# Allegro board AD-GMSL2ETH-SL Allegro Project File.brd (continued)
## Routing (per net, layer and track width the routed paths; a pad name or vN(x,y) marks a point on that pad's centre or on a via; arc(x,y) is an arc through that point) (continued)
B_SIOAN: length 2
  BOTTOM w0.127: C57.1 114.18,33.74 U2.22
B_SIOAP: length 2
  BOTTOM w0.127: U2.23 113.8,33.42 C63.2
B_SIOBN: length 2
  BOTTOM w0.127: U2.19 115.25,34.8 C58.1
B_SIOBP: length 2
  BOTTOM w0.127: C64.2 115.62,35.14 U2.18
B_SIOCN: length 2
  BOTTOM w0.127: C59.1 114.92,41.44 U2.9
B_SIOCP: length 2
  BOTTOM w0.127: C61.2 115.25,41.06 U2.10
B_SIODN: length 2
  BOTTOM w0.127: U2.6 113.84,42.48 C60.1
B_SIODP: length 2
  BOTTOM w0.127: C62.2 113.5,42.85 U2.5
B_VDD18: length 29.2
  TOP w0.483: C80.1 C79.1 v1(112.57,35.84) ; v1(112.21,40.38) 111.88,40.05 C67.1 C66.1
  TOP w0.508: 113.11,35.3 112.58,35.84 v1(112.57,35.84) ; 112.24,41.6 111.29,40.65 C66.1
  TOP w0.61: 113.11,35.3 113.52,34.9 118.68,34.9 119.04,35.26 C154.1 ; 112.24,41.6 114.2,43.56 C65.1 R22.2
  L3_SIG w0.508: v1(112.21,40.38) 111.86,40.03 111.86,39.73 113.31,38.28 113.31,37.56 112.24,36.5 112.24,36.17 v1(112.57,35.84)
  BOTTOM w0.305: U2.7 112.5,40.43 112.26,40.43 v1(112.21,40.38) ; U2.21 112.85,35.79 112.62,35.79 v1(112.57,35.84)
B_VPOC_1: length 4.5
  TOP w0.305: 139.47,17.86 139.88,18.27 U13.6
  TOP w0.508: C89.1 139.47,17.15 139.47,17.86
  TOP w0.762: R216.1 C89.1
B_VPOC_2: length 4.6
  TOP w0.305: 139.5,23.5 139.88,23.11 U13.20
  TOP w0.508: C88.1 139.5,24.01 139.5,23.5
  TOP w0.762: C88.1 138.92,24.55 R231.1
B_VPOC_3: length 4.5
  TOP w0.305: 140.77,17.86 140.38,18.24 U13.7
  TOP w0.508: C90.1 140.77,17.15 140.77,17.86
  TOP w0.762: R214.1 C90.1
B_VPOC_4: length 4.7
  TOP w0.305: 140.79,23.5 140.38,23.09 U13.19
  TOP w0.508: C91.1 140.79,24.03 140.79,23.5
  TOP w0.762: C91.1 141.34,24.55 R215.1
B_VTERM: length 1.3
  BOTTOM w0.305: 108.89,32.22 108.89,32.58 U2.30
BTN0_USER: length 55.8
  TOP w0.203: P5.C52 v2(100.77,28.95)
  TOP w0.508: v1(137.44,12.55) R218.2 S3.2 S3.1
  BOTTOM w0.305: v2(100.77,28.95) 103.13,28.95 104.29,27.79 104.29,25.25 107.82,21.72 115.67,21.72 118.77,18.62 131.37,18.62 v1(137.44,12.55)
EN_5V0: length 79.6
  TOP w0.305: v1(35.81,47.34) 36.22,47.75 U21.10 ; U10.20 v1(33.1,90.3)
  L8_SIG w0.508: v1(35.81,47.34) 32.68,50.46 32.68,67.68 27.01,73.36 27.01,89.01 29.09,91.1 29.09,91.11 29.5,91.52 32.82,91.52 33.18,91.16 33.18,90.38 v1(33.1,90.3)
  BOTTOM w0.508: v1(35.18,109.8) 32.46,107.09 32.46,100.84 35.18,98.12 35.18,92.37 v1(33.1,90.3)
EN_I2C_ALT: length 68.4
  TOP w0.203: U25.5 v2(117.93,22.82) 104.84,22.82 P5.A54 ; v1(113.99,66.63) R41.2 U20.5
  L3_SIG w0.203: v1(113.99,66.63) 113.99,56.76 120.82,49.93 120.82,46.21 119.96,45.35 119.96,32.99 120.49,32.46 120.49,28.53 118.58,26.63 118.58,23.39 118.02,22.82 v2(117.93,22.82)
EN_VIO: length 46.9
  TOP w0.254: v1(15.01,45.75) v1(23.83,45.75) 26.44,43.13 31.78,43.13 32.71,44.06 v1(32.71,44.97) 34.59,44.97 36.42,43.13 40.71,43.13 41.6,44.03 v1(41.6,44.97) 46.22,49.59 R220.2 U26.6 47.96,50.39 48.21,50.64 48.21,51.43 47.96,51.69 U26.4
  BOTTOM w0.254: v1(32.71,44.97) 32.97,44.71 U18.1 ; v1(15.01,45.75) 15.01,45.06 15.19,44.88 U4.1 ; v1(41.6,44.97) 41.86,44.71 U5.1 ; v1(23.83,45.75) 23.83,44.96 24.08,44.71 U6.1
FAN_PWM: length 52.5
  TOP w0.203: P3.C23 v2(82.04,94.6)
  BOTTOM w0.305: R98.1 61.76,53.73 62.28,54.25 62.28,69.6 82.04,89.36 v2(82.04,94.6)
FAN_TACH: length 54.4
  TOP w0.203: P3.C22 v2(81.4,94.6)
  TOP w0.305: v1(61.65,56.79) R104.1
  TOP w0.356: R103.2 54.38,56.86 R104.1
  BOTTOM w0.305: v1(61.65,56.79) 61.65,70.02 81.4,89.77 v2(81.4,94.6)
GPIO_0: length 71.5
  TOP w0.203: P3.A15 v2(76.96,92.06)
  TOP w0.508: D7.3 v1(17.43,70.79)
  TOP w0.61: D7.3 RT3.2
  L3_SIG w0.203: v1(17.43,70.79) 17.98,71.35 24.14,71.35 30.72,77.93 42.74,77.93 48.48,83.67 69.27,83.67 76.96,91.36 v2(76.96,92.06)
GPIO_1: length 77.3
  TOP w0.203: P3.A16 v2(77.59,92.06)
  TOP w0.508: D8.3 v1(17.43,73.79)
  TOP w0.61: D8.3 RT4.2
  L3_SIG w0.203: v2(77.59,92.06) 77.59,91.18 69.49,83.08 48.74,83.08 43,77.34 30.92,77.34 23.81,70.23 16.87,70.23 16.46,70.64 16.46,72.82 v1(17.43,73.79)
GPIO_2: length 85.8
  TOP w0.203: P3.A17 v2(78.23,92.06)
  TOP w0.508: D9.3 v1(17.43,80.04)
  TOP w0.61: D9.3 RT5.2
  L3_SIG w0.203: v1(17.43,80.04) 15.85,78.46 15.85,70.33 16.41,69.77 24.09,69.77 31.08,76.76 43.28,76.76 49.02,82.5 69.75,82.5 78.23,90.98 v2(78.23,92.06)
GPIO_3: length 78.8
  TOP w0.203: P3.B16 v2(77.59,93.9)
  TOP w0.508: D10.3 v1(17.43,83.19)
  TOP w0.61: D10.3 RT6.2
  L3_SIG w0.203: v1(17.43,83.19) 18.62,81.99 18.62,75.74 19.6,74.76 25.16,74.76 30.09,79.68 40.67,79.68 46.39,85.4 68.44,85.4 74.88,91.85 74.88,92.84 75.5,93.46 77.39,93.46 77.59,93.66 v2(77.59,93.9)
GPIO_4: length 84.5
  TOP w0.203: P3.B17 v2(78.23,93.99)
  TOP w0.508: D11.3 v1(17.43,86.33)
  TOP w0.61: D11.3 RT7.2
  L3_SIG w0.203: v2(78.23,93.99) 78.23,93.62 77.61,93.01 75.84,93.01 75.36,92.53 75.36,91.44 68.75,84.83 46.63,84.83 40.92,79.11 30.41,79.11 25.59,74.3 19.18,74.3 18.01,75.46 18.01,81.41 16.51,82.91 16.51,85.42 v1(17.43,86.33)
GPIO_5: length 87.2
  TOP w0.203: P3.B18 78.86,93.8 79.09,94.03 v2(79.81,94.03)
  TOP w0.508: D12.3 v1(17.43,89.48)
  TOP w0.61: D12.3 RT8.2
  L3_SIG w0.203: v1(17.43,89.48) 18.35,88.56 20.62,88.56 21.46,87.71 21.46,83.54 22.17,82.83 27.66,82.83 30.02,85.19 33.25,85.19 34.16,84.28 39.24,84.28 44.73,89.76 61.21,89.76 62.61,91.16 62.61,95.22 65.86,98.48 80.01,98.48 81.38,97.1 81.38,95.69 80.62,94.93 80.62,94.23 80.42,94.03 v2(79.81,94.03)
GPIO_6: length 74.9
  TOP w0.203: P3.C18 v2(78.86,94.6)
  TOP w0.508: D14.3 v1(20.25,72.21)
  TOP w0.61: D14.3 RT11.2
  L3_SIG w0.203: v1(20.25,72.21) 20.93,72.9 25.01,72.9 30.64,78.53 41.21,78.53 46.91,84.23 69,84.23 75.84,91.07 75.84,92.23 76.23,92.61 77.8,92.61 78.86,93.67 v2(78.86,94.6)
GPIO_7: length 76.9
  TOP w0.203: P3.C19 v2(79.5,94.6)
  TOP w0.61: D15.3 19.7,76.12 v1(19.3,76.12) RT12.2
  L3_SIG w0.203: v1(19.3,76.12) 21.01,76.12 22.12,77.24 26.78,77.24 30.34,80.8 39.53,80.8 45.58,86.85 62.52,86.85 65.58,89.92 65.58,94.69 66.47,95.58 78.94,95.58 79.5,95.02 v2(79.5,94.6)
GPIO_8: length 77.1
  TOP w0.203: P3.C20 v2(80.13,94.6)
  TOP w0.61: D16.3 19.7,77.7 v1(19.3,77.7) RT13.2
  L3_SIG w0.203: v2(80.13,94.6) 80.13,94.97 79.12,95.99 66.19,95.99 65.02,94.82 65.02,90.2 62.23,87.4 45.37,87.4 39.32,81.36 30.19,81.36 26.53,77.7 v1(19.3,77.7)
GPIO_9: length 74.3
  TOP w0.203: P3.D16 v2(77.59,96.53)
  TOP w0.508: D17.3 v1(20.25,81.7)
  TOP w0.61: D17.3 RT14.2
  L3_SIG w0.203: v1(20.25,81.7) 22.16,79.78 27.8,79.78 29.96,81.94 39.17,81.94 45.2,87.97 62.01,87.97 64.41,90.37 64.41,94.87 66.72,97.17 77.28,97.17 77.59,96.85 v2(77.59,96.53)
GPIO_10: length 77.1
  TOP w0.203: P3.D17 v2(78.23,96.53)
  TOP w0.508: D18.3 v1(20.25,84.76)
  TOP w0.61: D18.3 RT15.2
  L3_SIG w0.203: v1(20.25,84.76) 20.25,82.8 22.73,80.31 27.52,80.31 29.73,82.52 38.99,82.52 45.04,88.57 61.75,88.57 63.8,90.63 63.8,94.95 66.48,97.62 77.56,97.62 78.23,96.95 v2(78.23,96.53)
GPIO_11: length 79.2
  TOP w0.203: P3.D18 v2(78.86,96.53)
  TOP w0.508: D19.3 v1(20.25,87.91)
  TOP w0.61: D19.3 RT16.2
  L3_SIG w0.203: v2(78.86,96.53) 78.86,97.11 77.9,98.07 66.19,98.07 63.2,95.07 63.2,90.88 61.48,89.17 44.9,89.17 39.48,83.74 29.44,83.74 27.86,82.17 21.82,82.17 20.87,83.12 20.87,87.28 v1(20.25,87.91)
GTH_REFLCK_N: length 99.9
  TOP w0.203: P5.C4 v4(70.29,28.95)
  L3_SIG w0.203: v1(103.3,104.09) 103.3,101.13 102.22,100.05 102.22,98.43 101.45,97.66 96.24,97.66 95.21,96.63 95.21,92.47 67.77,65.03 67.77,27.99 68.51,27.25 69.54,27.25 70.17,27.89 70.17,28.56 70.29,28.68 v4(70.29,28.95)
  BOTTOM w0.203: C128.2 102.78,103.57 v1(103.3,104.09)
GTH_REFLCK_P: length 93.6
  TOP w0.203: P5.C3 v4(69.66,28.95)
  L3_SIG w0.203: v4(69.66,28.95) 69.66,28.67 69.78,28.55 69.78,28.09 69.36,27.67 68.68,27.67 68.19,28.17 68.19,64.78 95.63,92.22 95.63,96.46 96.41,97.24 101.63,97.24 102.64,98.25 102.64,99.62 v1(103.25,100.23)
  BOTTOM w0.203: C127.2 v1(103.25,100.23)
I2C_EXP_RSTB: length 59.1
  TOP w0.203: R121.2 v2(132.82,58.01) 133.43,58.62 U19.24 ; P5.C51 v2(100.14,28.95)
  L8_SIG w0.203: v2(132.82,58.01) 132.82,56.67 133.27,56.21 133.27,53.87 118.17,38.76 117.5,38.76 115.7,40.56 114.73,40.56 114.33,40.16 114.33,38.99 115.47,37.85 115.47,30.78 115.04,30.35 106.18,30.35 105.24,29.41 100.34,29.41 100.14,29.21 v2(100.14,28.95)
I2C_MASTER_SCL: length 3.9
  TOP w0.203: U3.33 95.61,110.66 v2(95.86,110.91) 96.1,111.15 R45.2
  BOTTOM w0.203: v2(95.86,110.91) 96.36,111.41 R54.2
I2C_MASTER_SDA: length 3.9
  TOP w0.203: R42.2 94.12,111.15 v2(94.36,110.91) 94.61,110.66 U3.35
  BOTTOM w0.203: R58.2 93.86,111.41 v2(94.36,110.91)
I2C_SCK: length 55.2
  TOP w0.203: R119.2 v2(130.61,61.72) R122.1 ; P5.D49 98.55,29.44 98.78,29.67 98.78,30.45 v2(99.59,31.27)
  L8_SIG w0.203: v2(99.59,31.27) 99.59,35.38 103.23,39.01 105.61,39.01 109.6,43 121.23,43 129.29,51.06 129.29,60.4 v2(130.61,61.72)
I2C_SDA: length 54.3
  TOP w0.203: v2(99.59,30.61) 99.18,30.21 P5.D50 ; R123.1 131.31,60.93 v2(130.61,60.93) 130.61,60.94 R120.2
  L8_SIG w0.203: v2(130.61,60.93) 129.72,60.05 129.72,50.89 121.4,42.57 109.8,42.57 105.84,38.61 103.41,38.61 100.1,35.3 100.1,30.82 99.9,30.61 v2(99.59,30.61)
JTAG_TCK: length 45.3
  TOP w0.203: P3.A25 83.31,88.8 80.98,86.46 57.76,86.46 54.38,83.08 51.05,83.08 50.65,83.49 50.65,87.76 50.97,88.08 P7.6
JTAG_TDI: length 35.6
  TOP w0.203: P3.A24 82.67,89.13 80.65,87.1 57.48,87.1 54.46,84.08 P7.10
JTAG_TDO: length 34
  TOP w0.203: P7.8 55.5,86.08 57.15,87.73 80.34,87.73 82.04,89.43 P3.A23
JTAG_TMS: length 32.9
  TOP w0.203: P7.4 55.49,90.08 57.2,88.37 80.04,88.37 81.4,89.74 P3.A22
LDO_OUT: length 1.3
  TOP w0.483: R239.2 40.16,49.47 C249.1
LED0_USER: length 11.4
  TOP w0.203: P5.B53 101.4,26.42 v2(102.03,26.42)
  TOP w0.406: v1(102.03,20.22) 100.84,20.22 100.32,19.7 R152.1 Q3.1
  L8_SIG w0.305: v1(102.03,20.22) v2(102.03,26.42)
MIO36_TXD: length 94
  TOP w0.203: v2(95.23,19.78) 95.23,18.93 90.78,14.47 U24.8 ; P3.B29 v2(85.85,93.99)
  BOTTOM w0.203: v2(95.23,19.78) 92.21,19.78 90.02,21.97 90.02,38.81 82.5,46.33 82.5,85.73 86.98,90.21 86.98,92.29 85.85,93.42 v2(85.85,93.99)
MIO37_RXD: length 92.2
  TOP w0.203: P3.B30 v2(86.48,93.99) ; v2(94.72,20.31) 94.72,19.13 90.57,14.97 U24.9
  BOTTOM w0.203: v2(94.72,20.31) 92.42,20.31 90.54,22.19 90.54,39.03 83.02,46.55 83.02,85.51 87.42,89.9 87.42,92.59 86.48,93.52 v2(86.48,93.99)
OUT0_A_N: length 4
  TOP w0.203: U3.12 99.61,102.11 99.81,101.9 v2(100.33,101.9)
  BOTTOM w0.203: v2(100.33,101.9) 101.94,101.9 R53.2 102.15,102.11 C128.1
OUT0_A_P: length 4.8
  TOP w0.203: v2(100.33,101.3) 99.8,101.3 99.11,101.98 U3.11
  BOTTOM w0.203: C127.1 102.15,101.09 R52.1 101.94,101.3 v2(100.33,101.3)
OUT0_B_N: length 6
  TOP w0.203: R91.1 R87.2 104.56,102.31 104.27,102.31 102.3,104.27 U3.15
OUT0_B_P: length 6
  TOP w0.203: U3.14 102.1,103.77 104.07,101.8 104.56,101.8 R86.1 R90.1
OUT0_C_N: length 5.4
  TOP w0.203: C150.1 104.81,106.05 R208.2 104.54,105.77 U3.18
OUT0_C_P: length 5.4
  TOP w0.203: U3.17 104.54,105.27 R207.2 104.81,105 C149.1
OUT1_A_N: length 4.6
  TOP w0.203: U3.26 99.11,110.06 99.8,110.75 v2(100.33,110.75)
  BOTTOM w0.203: v2(100.33,110.75) 101.92,110.75 R47.2 R140.1
OUT1_A_P: length 3.7
  TOP w0.203: U3.25 99.61,109.94 99.81,110.14 v2(100.33,110.14)
  BOTTOM w0.203: R217.1 R46.1 101.93,110.14 v2(100.33,110.14)
OUT1_B_N: length 5.5
  TOP w0.203: R144.1 R128.2 104.56,109.19 103.3,109.19 102.38,108.27 U3.23
OUT1_B_P: length 5.5
  TOP w0.203: U3.22 102.59,107.77 103.5,108.69 104.56,108.69 R92.1 R143.1
PGOOD_VIO: length 142.8
  TOP w0.305: v1(41.19,41.33) v1(32.3,41.33) v1(23.41,41.33) v1(14.52,41.33)
  TOP w0.508: R248.2 123.8,18.01 Q13.1 v1(122.07,17.62)
  BOTTOM w0.254: U5.9 v1(41.19,41.33) ; v1(32.3,41.33) U18.9 ; v1(23.41,41.33) U6.9 ; v1(14.52,41.33) U4.9
  BOTTOM w0.305: v1(122.07,17.62) 121.55,17.09 90.63,17.09 86.89,20.83 86.89,37.38 83.94,40.34 58.22,40.34 52.76,34.87 43.21,34.87 41.19,36.89 v1(41.19,41.33)
PS_ERROR_OUT: length 102
  TOP w0.203: P3.B24 v2(82.67,93.99)
  TOP w0.406: Q6.1 R199.1 v1(108.02,19.7)
  BOTTOM w0.305: v1(108.02,19.7) 106.08,17.75 90.92,17.75 88.01,20.67 88.01,37.91 80.34,45.58 80.34,86.64 82.67,88.97 v2(82.67,93.99)
PS_ERROR_STATUS: length 109
  TOP w0.203: P3.B25 v2(83.31,93.99)
  TOP w0.406: Q12.1 R201.1 v1(115.71,19.67)
  BOTTOM w0.305: v1(115.71,19.67) 115.01,20.37 107.77,20.37 105.79,18.39 91.19,18.39 88.65,20.93 88.65,38.17 80.97,45.84 80.97,86.41 83.31,88.75 v2(83.31,93.99)
PS_MIO39_501_SDIO_SEL: length 114.4
  TOP w0.203: P3.B33 v2(88.07,93.98)
  L8_SIG w0.203: v2(88.07,93.98) 88.07,92.56 85.05,89.54 81.65,89.54 59.09,66.97 59.09,39.11 55.58,35.6 55.58,16.98 56.56,15.99 73.27,15.99 v7(75.16,17.88)
  BOTTOM w0.203: U22.E3 v7(75.16,17.88)
PS_MIO45_501_SDIO_DETECT: length 138.2
  TOP w0.203: v1(55.73,6.3) 63.65,6.3 72.64,15.29 72.64,18.05 72.89,18.3 v5(73.35,18.3) ; P3.D33 v2(88.39,96.53)
  L8_SIG w0.203: v5(73.35,18.3) 73.34,18.28 73.05,18.28 72.77,18.01 72.77,17.45 72.51,17.19 57.81,17.19 57.05,17.95 57.05,36.5 59.49,38.94 59.49,66.8 81.82,89.13 85.32,89.13 88.7,92.51 88.7,95.83 88.39,96.14 v2(88.39,96.53)
  BOTTOM w0.508: v1(55.73,6.3) R136.2 P9.A
PS_MIO46_501_SDIO_DAT0: length 92.3
  L8_SIG w0.102: v7(75.78,20.06) 75.11,20.73 68,20.73 64.98,23.75 64.98,66.64 80.38,82.04 v7(85.21,82.04)
  BOTTOM w0.127: U22.D1 74.16,18.97 74.68,19.48 R332.2 v7(75.78,20.06) ; v7(85.21,82.04) 84.8,82.04 84.54,82.3 84.54,85.67 84.94,86.07 R164.1
PS_MIO47_501_SDIO_DAT1: length 96
  L8_SIG w0.102: v7(85.24,81.01) 80.14,81.01 65.53,66.41 65.53,23.97 68.48,21.03 75.46,21.03 76.35,20.14 76.35,19.2 75.78,18.63 v7(75.78,18.11)
  BOTTOM w0.127: R162.1 93.24,83.02 91.23,81.01 v7(85.24,81.01) ; v7(75.78,18.11) R132.2 U22.E1
PS_MIO48_501_SDIO_DAT2: length 91.7
  L8_SIG w0.102: v7(71.58,19.35) 71.25,19.35 71.09,19.51 65.98,19.51 62.74,22.75 62.74,67.56 80.69,85.51 v7(85.13,85.51)
  BOTTOM w0.127: v7(85.13,85.51) 88.67,85.51 88.92,85.76 R161.1 ; U22.A1 72.96,18.86 72.47,19.35 v7(71.58,19.35) R131.2
PS_MIO49_501_SDIO_DAT3: length 92
  L8_SIG w0.102: v7(73.05,19.56) 73.02,19.56 72.77,19.81 66.48,19.81 63.3,23 63.3,67.32 80.59,84.62 v7(85.16,84.62)
  BOTTOM w0.127: R130.2 v7(73.05,19.56) 73.36,19.25 U22.B1 ; R163.1 89.78,85.6 88.8,84.62 v7(85.16,84.62)
PS_MIO50_501_SDIO_CMD: length 92.6
  L8_SIG w0.102: v7(85.2,83.85) 80.61,83.85 63.86,67.09 63.86,23.24 66.98,20.12 73.25,20.12 v7(73.76,19.61)
  BOTTOM w0.127: v7(85.2,83.85) 89.36,83.85 90.65,85.14 R160.1 ; R333.2 v7(73.76,19.61) U22.C1
PS_MIO51_501_SDIO_CLK: length 98.3
  L8_SIG w0.102: v7(85.21,82.88) 80.43,82.88 64.42,66.87 64.42,23.5 67.5,20.42 73.63,20.42 74.46,19.59 74.46,18.58 v5(74.17,18.3)
  BOTTOM w0.127: R159.1 92.38,84.02 91.24,82.88 89.02,82.88 88.89,82.75 88.89,81.97 88.77,81.85 88.51,81.85 88.39,81.97 88.39,82.75 88.26,82.88 88,82.88 87.88,82.75 87.88,81.97 87.75,81.85 87.5,81.85 87.37,81.97 87.37,82.75 87.24,82.88 86.99,82.88 86.86,82.75 86.86,81.97 86.73,81.85 86.48,81.85 86.35,81.97 86.35,82.75 86.23,82.88 v7(85.21,82.88)
PS_MODE0: length 166.9
  TOP w0.203: P3.A27 v2(84.58,92.06)
  L8_SIG w0.203: v2(84.58,92.06) 84.58,91.69 84.07,91.19 80.98,91.19 57.46,67.67 57.46,39.78 52.55,34.87 52.55,13.95 56.82,9.68 109.68,9.68 113.92,5.44 119.04,5.44 S2.1A
PS_MODE1: length 169
  TOP w0.203: P3.A28 v2(85.21,92.06)
  L8_SIG w0.203: S2.2A 121.17,5.84 114.09,5.84 109.85,10.08 56.99,10.08 52.96,14.12 52.96,34.71 57.87,39.62 57.87,67.48 81.15,90.75 84.25,90.75 85.21,91.72 v2(85.21,92.06)
PS_MODE2: length 171.2
  TOP w0.203: P3.A29 v2(85.85,92.06)
  L8_SIG w0.203: S2.3A 123.31,6.25 114.26,6.25 110.02,10.49 57.16,10.49 53.37,14.28 53.37,34.54 58.27,39.45 58.27,67.31 81.31,90.35 84.51,90.35 85.85,91.69 v2(85.85,92.06)
PS_MODE3: length 173.4
  TOP w0.203: P3.A30 v2(86.48,92.06)
  L8_SIG w0.203: S2.4A 125.44,6.65 114.43,6.65 110.19,10.9 57.33,10.9 53.77,14.45 53.77,34.37 58.68,39.28 58.68,67.14 81.48,89.94 84.79,89.94 86.48,91.64 v2(86.48,92.06)
PS_POR_L: length 167.5
  TOP w0.203: P3.C15 v2(76.96,94.6)
  TOP w0.508: S6.2 v2(109,8) S6.1
  L8_SIG w0.203: v2(109,8) 85.7,8 84.48,6.78 58.39,6.78 50.93,14.25 50.93,35.59 55.93,40.59 55.93,84.23 64.99,93.29 75.68,93.29 76.96,94.56 v2(76.96,94.6)
PS_SRST_B: length 156.6
  TOP w0.203: P3.C16 v2(77.59,94.6)
  TOP w0.508: S1.2 v2(98.43,9.12) S1.1
  L8_SIG w0.203: v2(77.59,94.6) 77.59,94.56 75.87,92.84 65.18,92.84 56.34,84 56.34,40.42 51.36,35.44 51.36,14.45 58.62,7.19 84.3,7.19 85.52,8.41 97.72,8.41 v2(98.43,9.12)
PWROFF_C2M_L: length 123.9
  TOP w0.203: P3.B26 v2(83.94,93.99)
  TOP w0.305: R249.1 R100.2 25.73,89.49 v1(25.73,90.12)
  L8_SIG w0.406: v2(83.94,93.99) 83.94,96.29 82.4,97.84 67.26,97.84 64.87,100.23 34.55,100.23 25.73,91.41 25.73,90.13 v1(25.73,90.12)
  L8_SIG w0.508: v1(38.42,47.22) 38.41,47.22 36.94,45.75 34.68,45.75 30.88,49.54 30.88,66.4 24.94,72.34 24.94,88.61 25.73,89.4 v1(25.73,90.12)
  BOTTOM w0.483: R250.1 v1(38.42,47.22)
REF_AD9545_EXT: length 28.3
  TOP w0.203: U3.38 91.77,108.27 88.19,111.85 70.79,111.85 68.99,110.06 68.99,108.61 R31.2
REF_AD9545_PL: length 31.6
  TOP w0.203: R188.1 88.45,101.74 88.06,101.35 v2(67.51,101.35) ; P3.B1 v2(68.07,93.99)
  BOTTOM w0.203: v2(67.51,101.35) 67.51,97.89 68.53,96.88 68.53,94.19 68.33,93.99 v2(68.07,93.99)
REF_PPS_IN: length 27.5
  TOP w0.203: R37.2 69.49,108.6 69.49,109.86 70.99,111.35 87.99,111.35 91.57,107.77 U3.39
RESETB_AD9545: length 30.7
  TOP w0.203: U3.48 92.99,103.27 92.3,102.59 92.3,101.47 91.8,100.97 R191.2 91.22,100.53 91.01,100.33 v2(71.78,100.33) ; P3.B7 71.88,94.24 v2(71.58,94.54)
  BOTTOM w0.203: v2(71.78,100.33) 71.78,94.74 v2(71.58,94.54)
RXD_FT232: length 5.7
  TOP w0.203: U24.3 84.38,13.97 83.71,13.3 83.71,13.02 v2(84.58,12.14)
  BOTTOM w0.203: U23.2 v2(84.58,12.14)
SCL_A_ALT: length 106.2
  TOP w0.203: D21.3 20.25,65.15 20.98,64.41 24.23,64.41 25.68,65.86 47.53,65.86 49.41,63.98 115.7,63.98 116.45,64.74 R124.2 116.56,65.69 U20.6
  TOP w0.61: RT9.2 D21.3
SCL_A_VCAM: length 56
  TOP w0.203: U19.2 135.22,57.27 134.98,57.02 v2(133.73,57.02) 133.73,56.57 134.7,55.6 R179.2 ; U12.14 143.46,98.22 144.3,99.06 v2(144.3,99.32)
  L8_SIG w0.203: v2(133.73,57.02) 134.11,57.41 134.11,67.02 136.36,69.26 136.36,88.57 137.16,89.38 142.28,89.38 144.3,91.4 v2(144.3,99.32)
SCL_B_ALT: length 168.9
  TOP w0.203: v1(118.75,21.13) 118.75,21.75 R155.2 118.92,21.93 U25.6
  TOP w0.508: D24.3 v1(20.25,69.06)
  TOP w0.61: D24.3 RT10.2
  L3_SIG w0.203: v1(20.25,69.06) 21.59,67.72 45.7,67.72 48.83,64.59 52.86,64.59 54.81,62.64 54.81,12.25 59.87,7.2 108.97,7.2 118.75,16.98 v1(118.75,21.13)
SCL_B_VCAM: length 44.6
  TOP w0.203: v2(144.81,22.28) 144.35,22.28 143.25,21.18 U13.14 ; U19.4 136.22,55.95 136.41,55.77 v2(136.41,55.7) 136.41,55.17 R184.2
  L8_SIG w0.203: v2(136.41,55.7) 136.4,55.7 136.19,55.5 136.19,32.03 138.13,30.1 142.01,30.1 144.81,27.3 v2(144.81,22.28)
SCL_TEMP1: length 11.1
  TOP w0.203: U19.13 137.22,62.5 v2(137.49,62.76) 137.49,63.33 R80.2
  BOTTOM w0.203: v2(137.49,62.76) 138.15,62.76 138.48,62.43 138.48,56.95 140.14,55.29 U7.B2
SCL_TEMP2: length 67.7
  TOP w0.203: v1(140.05,64.19) 140.04,64.19 139.89,64.35 139.89,66.62 139.35,67.16 139.34,67.16 139.05,67.46 133.03,67.46 129.89,64.32 123.85,64.32 121.82,62.29 113.24,62.29 104.72,53.77 87.65,53.77 U8.B2 ; U19.15 136.22,62.48 v2(135.94,62.76) 135.94,63.33 R81.2
  L3_SIG w0.203: v2(135.94,62.76) 138.03,64.85 139.53,64.85 140.05,64.34 v1(140.05,64.19)
SDA_A_ALT: length 107.6
  TOP w0.203: D20.3 17.43,63.55 18.08,62.89 23.6,62.89 25.93,65.23 47.27,65.23 49.15,63.35 115.98,63.35 117.16,64.53 R56.2 117.06,65.68 U20.7
  TOP w0.61: D20.3 RT1.2
SDA_A_VCAM: length 57.4
  TOP w0.203: U12.13 143.64,97.72 144.81,98.88 v2(144.81,99.85) ; U19.1 134.69,57.91 v2(133.6,57.91) 133.2,57.51 133.2,56.52 133.86,55.86 R183.2
  L8_SIG w0.203: v2(144.81,99.85) 144.1,99.85 143.79,99.53 143.79,91.88 141.82,89.92 136.92,89.92 135.82,88.82 135.82,69.5 133.6,67.28 v2(133.6,57.91)
SDA_B_ALT: length 169.6
  TOP w0.203: v1(119.61,21.13) 119.61,21.73 R69.2 119.42,21.92 U25.7
  TOP w0.508: D22.3 v1(17.43,67.49)
  TOP w0.61: D22.3 RT2.2
  L3_SIG w0.203: v1(119.61,21.13) 119.61,16.94 109.27,6.6 59.57,6.6 54.18,11.99 54.18,62.33 52.55,63.96 48.56,63.96 45.44,67.08 17.83,67.08 v1(17.43,67.49)
SDA_B_VCAM: length 45.5
  TOP w0.203: U19.3 135.72,55.89 135.54,55.7 ; v2(144.81,21.67) 144.45,21.67 143.46,20.68 U13.13 ; 135.54,55.7 135.53,55.7 R203.2 ; 135.54,55.7 v2(135.54,55.71)
  L8_SIG w0.203: v2(144.81,21.67) 144.5,21.67 144.3,21.87 144.3,27.03 141.76,29.57 137.9,29.57 135.74,31.72 135.74,55.5 135.54,55.7 v2(135.54,55.71)
SDA_TEMP1: length 12
  TOP w0.203: U19.12 v2(137.97,61.59) R82.2
  BOTTOM w0.203: U7.B1 140.6,54.79 139.88,54.79 137.97,56.69 v2(137.97,61.59)
SDA_TEMP2: length 64.2
  TOP w0.203: U8.B1 105.07,53.35 108.61,56.89 113.54,61.82 121.95,61.82 124,63.87 130.15,63.87 133.24,66.96 138.6,66.96 139.39,66.17 139.39,64.63 v1(139.01,64.26) ; U19.14 v2(136.72,62.76) R83.2
  L3_SIG w0.203: v2(136.72,62.76) 138.22,64.26 v1(139.01,64.26)
SDIO_CLK: length 24.5
  TOP w0.127: v2(74.55,14.96) 74.55,15.55 74.8,15.8 75.44,15.8 75.69,16.05 75.69,16.54 75.43,16.8 74.42,16.8 74.17,17.05 v5(74.17,17.87)
  BOTTOM w0.127: v2(74.55,14.96) 74.55,12.65 72.97,11.07 64.07,11.07 63.08,12.07 P9.5
SDIO_CMD: length 23
  BOTTOM w0.127: P9.3 65.28,15.88 65.02,15.62 64.11,15.62 63.86,15.37 63.86,14.86 64.11,14.61 65.13,14.61 65.38,14.35 65.38,13.84 65.13,13.59 64.11,13.59 63.86,13.33 63.86,12.55 64.48,11.93 72.71,11.93 73.99,13.21 73.99,16.61 73.76,16.84 U22.C4
SDIO_DAT0: length 26.1
  BOTTOM w0.127: U22.D4 74.16,17.2 75.08,16.28 75.08,11.59 73.72,10.23 63.38,10.23 60.87,12.73 P9.7
SDIO_DAT1: length 29.3
  BOTTOM w0.127: P9.8 59.77,12.33 62.87,9.23 74.26,9.23 75.56,10.53 75.56,16.48 U22.E4
SDIO_DAT2: length 23.6
  BOTTOM w0.127: P9.1 67.47,17.68 67.22,17.93 65.76,17.93 65.51,18.18 65.51,18.69 65.76,18.95 67.08,18.95 67.34,19.2 67.34,19.71 67.08,19.96 65.76,19.96 65.51,20.22 65.51,20.8 65.77,21.07 68.02,21.07 68.35,20.74 68.35,15.49 68.66,15.19 70.54,15.19 70.87,15.52 70.87,16.79 71.22,17.14 72.62,17.14 U22.A4
SDIO_DAT3: length 23.1
  BOTTOM w0.127: P9.2 66.38,15.33 66.63,15.08 67.74,15.08 68.07,14.75 68.07,14.4 67.74,14.06 66.27,14.06 65.96,13.75 65.96,13.23 66.48,12.7 68.39,12.7 68.75,13.07 68.75,14.13 69,14.38 69.51,14.38 69.76,14.13 69.76,13.24 69.97,13.03 70.57,13.03 70.78,13.24 70.78,14.16 71.03,14.41 71.55,14.41 71.81,14.16 71.81,13.21 71.98,13.03 73.06,13.03 73.27,13.24 R135.2 73.36,14.92 U22.B4
SFP+_I2C_SCL_3V3: length 182.8
  TOP w0.203: R127.2 v2(138.07,55.7) 138.07,56.46 137.22,57.32 U19.6 ; P4.5 v1(33.43,25.14)
  L8_SIG w0.203: v1(33.43,25.14) 36.36,22.21 41.6,22.21 57.86,5.94 84.86,5.94 86.11,7.19 97.57,7.19 103.11,1.65 136.01,1.65 145.92,11.57 145.92,27.76 142.52,31.17 138.62,31.17 137.25,32.54 137.25,54.88 v2(138.07,55.7)
SFP+_I2C_SDA_3V3: length 182
  TOP w0.203: U19.5 136.72,57.1 137.24,56.59 v2(137.24,55.7) R133.2 ; P4.4 v1(33.43,25.94)
  L8_SIG w0.203: v1(33.43,25.94) 36.68,22.69 41.77,22.69 58.11,6.35 84.66,6.35 85.9,7.6 97.74,7.6 103.28,2.06 135.84,2.06 145.44,11.66 145.44,27.46 142.27,30.63 138.35,30.63 136.73,32.26 136.73,55.19 v2(137.24,55.7)
SFP+_LOS_3V3: length 5.3
  TOP w0.203: P4.8 v1(29.95,22.74)
  BOTTOM w0.203: v1(29.95,22.74) 29.42,22.74 28.62,21.94 TP2.1 R148.2
SFP+_MOD_DETECT_3V3: length 5.2
  TOP w0.203: P4.6 v1(29.95,24.34)
  BOTTOM w0.203: R150.2 TP3.1 28.45,23.75 29.04,24.34 v1(29.95,24.34)
SFP+_RS0_3V3: length 2.7
  TOP w0.203: P4.7 v1(32.79,23.54)
  BOTTOM w0.203: R60.1 R59.2 v1(32.79,23.54)
SFP+_RS1_3V3: length 2.8
  TOP w0.203: P4.9 v1(32.81,21.94)
  BOTTOM w0.203: v1(32.81,21.94) R62.1 R61.2
SFP+_RX_N: length 27.2
  TOP w0.095: P5.B2 68.19,26.38 arc(68.09,26.31) 67.97,26.29 67.08,26.29 arc(66.17,26.11) 65.39,25.59 62.45,22.65 arc(61.33,21.9) 60,21.63 48.39,21.63 arc(47.71,21.77) 47.14,22.15 47.09,22.2 arc(46.65,22.5) 46.12,22.6 44.23,22.6 arc(44.07,22.54) 44.01,22.37 C126.1
SFP+_RX_P: length 27.2
  TOP w0.095: C121.1 44.01,23.12 arc(44.07,22.96) 44.24,22.89 44.53,22.89 arc(44.72,22.97) 44.8,23.16 44.8,23.17 arc(45.07,23.44) 45.34,23.17 45.34,23.16 arc(45.42,22.97) 45.61,22.89 46.12,22.89 arc(46.76,22.76) 47.29,22.41 47.34,22.36 arc(47.82,22.03) 48.39,21.92 60,21.92 arc(61.22,22.16) 62.24,22.85 65.18,25.79 arc(66.06,26.37) 67.08,26.58 67.9,26.58 arc(67.96,26.59) 68.02,26.62 arc(68.06,26.68) 68.07,26.75 P5.B1
SFP+_TX_DISABLE: length 63.3
  TOP w0.203: v2(100.77,26.41) P5.B52
  TOP w0.356: Q2.1 R149.1 56.92,14.15 56.44,13.67 v1(56.44,12.65)
  L8_SIG w0.305: v1(56.44,12.65) 57.38,13.59 75.59,13.59 79.86,17.86 101.83,17.86 102.69,18.72 102.69,26.57 102.31,26.95 101.31,26.95 v2(100.77,26.41)
SFP+_TX_DISABLE_3V3: length 42.9
  TOP w0.203: v1(29.95,26.74) P4.3
  TOP w0.356: v1(58.88,19.82) 58.88,18.97 58.93,18.92 ; Q2.3 59.97,17.88 58.93,18.92 ; R251.1 58.93,18.92
  BOTTOM w0.356: v1(58.88,19.82) 58.87,19.83 57.07,19.83 53.85,16.61 43.03,16.61 35.36,24.28 35.36,25.78 34.4,26.74 v1(29.95,26.74) R146.2
SFP+_TX_FAULT_3V3: length 4
  TOP w0.203: v1(29.94,27.54) P4.2
  BOTTOM w0.203: v1(29.94,27.54) 29.13,28.35 TP1.1 R147.2
SFP+_TX_N: length 29.7
  TOP w0.095: C125.1 44.01,27.92 arc(44.07,27.76) 44.24,27.69 45.94,27.69 arc(46.56,27.81) 47.09,28.17 48.1,29.18 arc(48.73,29.6) 49.46,29.74 65.64,29.74 arc(66.71,29.47) 67.51,28.72 67.76,28.32 arc(67.99,28.08) 68.31,27.99 70.46,27.99 arc(70.89,27.81) 71.07,27.38 71.07,27.2 arc(71.09,27.08) 71.16,26.97 P5.B6
SFP+_TX_P: length 29.7
  TOP w0.095: P5.B5 70.69,26.97 arc(70.76,27.07) 70.78,27.2 70.78,27.38 arc(70.69,27.61) 70.46,27.7 68.31,27.7 arc(67.84,27.83) 67.51,28.18 67.27,28.57 arc(66.57,29.22) 65.64,29.46 49.46,29.46 arc(48.84,29.33) 48.31,28.98 47.85,28.52 47.3,27.97 arc(46.67,27.55) 45.94,27.4 45.42,27.4 arc(45.28,27.34) 45.22,27.2 arc(45.16,27.06) 45.02,27 44.88,27 arc(44.74,27.06) 44.68,27.2 arc(44.62,27.34) 44.48,27.4 44.23,27.4 arc(44.07,27.34) 44.01,27.17 C142.1
SPI_CS_AD9545: length 33.1
  TOP w0.203: v2(69.57,98.98) 70.59,97.97 89.08,97.97 89.61,97.43 94.28,97.43 95.33,98.48 R35.1 ; P3.B5 v2(70.61,93.99)
  BOTTOM w0.203: v2(70.61,93.99) 70.61,97.94 v2(69.57,98.98)
SPI_MISO: length 34.6
  TOP w0.203: P3.A3 v2(69.34,92.06) ; R32.1 90.69,98.82 89.74,99.77 71.53,99.77 70.56,100.74 v2(68.02,100.74)
  BOTTOM w0.203: v2(68.02,100.74) 68.02,98.17 68.96,97.23 68.96,93.35 69.34,92.97 v2(69.34,92.06)
SPI_MOSI: length 32.4
  TOP w0.203: R34.1 93.66,98.49 93.01,97.84 89.99,97.84 89.26,98.58 70.94,98.58 69.95,99.57 v2(69.04,99.57) ; P3.B4 v2(69.97,93.99)
  BOTTOM w0.203: v2(69.97,93.99) 69.97,97.79 69.04,98.73 v2(69.04,99.57)
SPI_SCL: length 34.8
  TOP w0.203: v2(68.53,100.18) 70.21,100.18 71.22,99.16 89.48,99.16 90.4,98.25 92.65,98.25 92.87,98.48 R33.1 ; P3.A4 v2(69.97,92.06)
  BOTTOM w0.203: v2(68.53,100.18) 68.53,98.45 69.47,97.51 69.47,93.57 69.98,93.07 69.98,92.06 v2(69.97,92.06)
TXD_FT232: length 6.1
  TOP w0.203: v2(82.21,14.5) 83.09,13.63 83.38,13.63 84.22,14.47 U24.2
  BOTTOM w0.203: U23.15 v2(82.21,14.5)
UART_RXD: length 126.1
  TOP w0.203: P3.D20 v2(80.13,96.53)
  TOP w0.508: D23.3 v1(17.43,53.31)
  TOP w0.61: RT17.1 D23.3
  L8_SIG w0.203: v2(80.13,96.53) 80.13,96.17 79.8,95.83 65.46,95.83 54.41,84.79 54.41,41.68 48.84,36.12 32.97,36.12 25.86,43.23 25.86,48.12 23.28,50.7 20.04,50.7 v1(17.43,53.31)
UART_TXD: length 132.8
  TOP w0.203: P3.D21 v2(80.77,96.53)
  TOP w0.508: D25.3 v1(17.43,57.99)
  TOP w0.61: D25.3 RT18.1
  L8_SIG w0.203: v2(80.77,96.53) 80.77,95.91 80.29,95.43 65.66,95.43 54.81,84.58 54.81,41.49 49.01,35.69 32.77,35.69 25.4,43.05 25.4,47.93 23.09,50.24 19.71,50.24 16.87,53.08 16.87,57.43 v1(17.43,57.99)
UNNAMED_2_ADMAX2008X_I77_ISET: length 2.4
  TOP w0.305: R157.1 142.34,95.34 142.1,95.59 U12.10
UNNAMED_2_ADMAX96724_I1_VDDIO: length 13.1
  TOP w0.483: v1(111.4,78.81) C20.1 C21.1
  TOP w0.508: 119.04,75.16 R4.1 ; 111.41,77.64 C21.1
  TOP w0.61: C22.1 112.35,76.69 111.41,77.64
  TOP w0.762: C22.1 119.04,75.16
  BOTTOM w0.305: v1(111.4,78.81) 111.84,78.81 U1.24
UNNAMED_2_ADMAX96724_I1_X1: length 6.6
  BOTTOM w0.152: U1.15 115.4,81.62 116.03,80.99 116.77,80.99 C10.1 119.3,83.52 Y1.1
UNNAMED_2_ADMAX96724_I1_X2: length 2.4
  BOTTOM w0.152: R3.2 116.71,80.51 115.8,80.51 U1.16
UNNAMED_2_ADMAX96724_I1_XRES: length 1.5
  TOP w0.483: v1(114.19,81.41) R2.2
  BOTTOM w0.305: v1(114.19,81.41) 114.19,81.41 U1.17
UNNAMED_2_CAP_I50_N1: length 2.4
  BOTTOM w0.152: Y1.3 118.83,82.06 C17.1 117.64,80.87 R3.1
UNNAMED_2_CAP_I106_N1: length 2.6
  TOP w0.356: R154.2 114.88,91.74 C153.1 R172.2
UNNAMED_2_RES_I103_N2: length 2.5
  TOP w0.356: R145.2 R168.2 R169.1
UNNAMED_2_RES_I104_N2: length 2.1
  TOP w0.305: R151.2 120.54,72.23 R170.2 R171.1
UNNAMED_3_ADMAX2008X_I69_ISET: length 2.2
  TOP w0.279: U13.10 142.25,18.71 142.6,18.36 R165.1
UNNAMED_3_ADMAX96724_I1_VDDIO: length 13.5
  TOP w0.483: v1(111.4,34.67) C81.1 C82.1
  TOP w0.508: v1(111.4,34.67) 111.88,34.19
  TOP w0.61: R25.1 119.69,30.68 119.04,31.33 C83.1 119.04,33.05 118.73,33.36 112.72,33.36 111.88,34.19
  BOTTOM w0.305: v1(111.4,34.67) 111.84,34.67 U2.24
UNNAMED_3_ADMAX96724_I1_X1: length 6.6
  BOTTOM w0.152: U2.15 115.4,37.48 116.03,36.86 116.77,36.86 C71.1 119.3,39.38 Y2.1
UNNAMED_3_ADMAX96724_I1_X2: length 2.4
  BOTTOM w0.152: U2.16 115.8,36.37 116.71,36.37 R24.2
UNNAMED_3_ADMAX96724_I1_XRES: length 1.5
  TOP w0.483: v1(114.19,37.28) R23.2
  BOTTOM w0.305: v1(114.19,37.28) 114.19,37.27 U2.17
UNNAMED_3_CAP_I74_N1: length 2.4
  BOTTOM w0.152: Y2.3 118.83,37.92 C78.1 117.64,36.73 R24.1
UNNAMED_3_CAP_I103_N1: length 2.8
  TOP w0.356: C155.1 115.73,49.07 R115.2 115.72,50.26 R187.2
UNNAMED_3_RES_I100_N2: length 2.6
  TOP w0.305: R156.2 115.72,47.72 R70.2 115.73,47.73 R176.1
UNNAMED_3_RES_I101_N2: length 2.1
  TOP w0.356: R186.2 110.96,31.15 R177.2 R178.1
UNNAMED_4_ICTCA9548A_I28_A0: length 5.3
  TOP w0.203: U19.22 133.21,59.62 132.59,59 130.86,59 130.53,59.33 R118.1 R117.2
UNNAMED_4_ICTCA9548A_I28_A1: length 4.8
  TOP w0.203: U19.23 133.29,59.12 132.77,58.6 131.66,58.6 131.47,58.4 R142.2
  TOP w0.254: R116.1 131.45,58.42 131.47,58.4
UNNAMED_4_ICTCA9548A_I28_A2: length 2.2
  TOP w0.203: U19.18 R114.1 R113.2
UNNAMED_4_ICTCA9548A_I28_SCL: length 2
  TOP w0.203: U19.19 133.52,61.12 133.1,61.54 132.39,61.54 R122.2
UNNAMED_4_ICTCA9548A_I28_SDA: length 1.9
  TOP w0.203: U19.20 133.97,60.63 133.3,60.63 132.99,60.94 R123.2
UNNAMED_5_CAP_I2_N1: length 38.7
  TOP w0.508: R198.2 143.74,103.29 R194.2
  TOP w0.762: R194.2 143.69,103.33 v1(143.69,104.72)
  L3_SIG w0.762: v1(122.52,93.73) 131.6,93.73 132.8,94.93 132.8,98.67 134.55,100.42 139.4,100.42 v1(143.69,104.72)
  BOTTOM w0.508: C40.1 C36.1 122.52,97.07 R213.1 ; C40.1 v1(122.52,93.73) ; C40.1 126.61,94.39 L4.1
UNNAMED_5_CAP_I7_N1: length 30.9
  TOP w0.508: R193.2 R197.2
  TOP w0.762: v1(143.87,89.46) R193.2
  L3_SIG w0.762: v1(122.75,89.46) v1(143.86,89.46)
  BOTTOM w0.508: C35.1 v1(122.75,89.46) ; C35.1 C39.1 122.76,88 122.76,87.09 122.52,86.85 R212.1 ; C35.1 123.5,88.85 123.5,88.85 L3.1
UNNAMED_5_CAP_I12_N1: length 40.4
  TOP w0.508: R196.2 134.16,99.77 134.67,100.28 R192.2
  TOP w0.762: v1(120.7,78.47) 124.94,78.47 129.87,83.4 129.87,96.58 131.9,98.61 R196.2
  BOTTOM w0.508: L2.1 125.1,75.29 123.99,76.4 C34.1 C38.1 122.52,78.18 R210.1
  BOTTOM w0.762: v1(120.7,78.47) 122.23,78.47 R210.1
UNNAMED_5_CAP_I31_N1: length 35.6
  TOP w0.508: R195.2 R189.2
  TOP w0.762: v1(122.32,70.4) 133.32,81.4 133.32,88.6 135.28,90.56 R195.2
  BOTTOM w0.508: R209.1 122.33,68.83 C33.1 C37.1 ; C37.1 L1.1 ; C37.1 v1(122.32,70.4)
UNNAMED_5_CAP_I42_N1: length 46.7
  TOP w0.762: R232.2 R215.2 143.66,28.18 141.86,29.98 133.31,29.98 124.73,38.56 124.73,47.17 v1(122.32,49.58)
  BOTTOM w0.508: C54.1 126.61,50.24 L16.1 ; C54.1 C50.1 122.32,53.07 R244.1 ; C54.1 v1(122.32,49.58)
UNNAMED_5_CAP_I47_N1: length 53.2
  TOP w0.762: v1(144.46,12.85) R235.2 R214.2
  L3_SIG w0.762: v1(122.8,45.39) 122.8,45.37 122.81,45.36 122.81,37 137.33,22.48 137.33,17.14 140.35,14.12 143.19,14.12 v1(144.46,12.85)
  BOTTOM w0.508: C49.1 C53.1 122.8,43.06 R236.1 ; C49.1 v1(122.8,45.39) ; C49.1 122.86,44.71 L15.1
UNNAMED_5_CAP_I52_N1: length 28
  TOP w0.762: v1(120.84,34.75) 124.09,34.75 132.59,26.25 R234.2 R231.2
  BOTTOM w0.508: R246.1 122.32,34.71 C52.1 C56.1 123.94,32.44 125.19,31.19 126.58,31.19 L18.1
  BOTTOM w0.762: v1(120.84,34.75) 122.29,34.75 R246.1
UNNAMED_5_CAP_I71_N1: length 32.5
  TOP w0.762: v1(133.92,13.33) 134.97,14.38 R233.2 R216.2
  L3_SIG w0.762: v1(122.33,26.23) 127.32,26.23 133.92,19.63 v1(133.92,13.33)
  BOTTOM w0.508: R245.1 122.32,22.69 C51.1 C55.1 ; C55.1 126.61,25.6 L17.1 ; C55.1 122.32,26.17 122.33,26.17 v1(122.33,26.23)
UNNAMED_5_CAP_I81_N2: length 0.8
  BOTTOM w0.305: R6.1 115.05,77.2 C41.2
UNNAMED_5_CAP_I86_N2: length 0.8
  BOTTOM w0.305: R7.1 115.91,78.06 C42.2
UNNAMED_5_CAP_I89_N2: length 0.8
  BOTTOM w0.305: C57.2 115.05,33.06 R14.1
UNNAMED_5_CAP_I91_N2: length 0.8
  BOTTOM w0.305: C58.2 115.91,33.92 R15.1
UNNAMED_5_CAP_I94_N2: length 0.8
  BOTTOM w0.305: R20.1 115.59,42.28 C59.2
UNNAMED_5_CAP_I96_N2: length 0.8
  BOTTOM w0.305: C60.2 114.72,43.14 R21.1
UNNAMED_5_CAP_I100_N2: length 0.8
  BOTTOM w0.305: C43.2 115.59,86.42 R12.1
UNNAMED_5_CAP_I102_N2: length 0.8
  BOTTOM w0.305: R13.1 114.72,87.28 C44.2
UNNAMED_5_CAP_I109_N1: length 37.4
  BOTTOM w0.127: C62.1 114.13,43.71 114.13,44.7 arc(114.29,45.52) 114.76,46.21 arc(117.17,47.82) 120,48.39 L37.2 135.76,48.39 arc(140.32,46.5) 142.2,41.94 142.2,41.64 arc(142.33,41.01) 142.68,40.48 arc(143.29,40.07) P2.3
UNNAMED_5_CAP_I110_N1: length 31.3
  BOTTOM w0.127: P2.4 138.03,39.93 arc(137.18,40.1) 136.47,40.58 arc(136.26,40.89) 136.19,41.25 136.19,45.71 arc(135.94,46.31) 135.34,46.56 L40.2 122.97,46.56 arc(122.6,46.53) 122.25,46.43 arc(122.14,46.37) 122.04,46.29 118.36,42.62 arc(117.34,41.93) C61.1
UNNAMED_5_CAP_I111_N1: length 30.9
  BOTTOM w0.127: C64.1 117.39,34.51 arc(117.65,34.45) 117.87,34.3 122.39,29.79 arc(122.56,29.64) 122.74,29.51 123.01,29.36 arc(123.13,29.3) 123.25,29.27 123.66,29.21 arc(123.68,29.21) 123.7,29.21 135.14,29.21 arc(135.57,29.29) 135.93,29.54 arc(136.18,29.92) 136.27,30.37 136.27,33.39 arc(136.49,34.47) 137.1,35.39 137.2,35.49 arc(137.69,35.82) 138.26,35.93 P2.1
UNNAMED_5_CAP_I112_N1: length 37.5
  BOTTOM w0.127: C63.1 114.44,31.31 arc(114.59,30.58) 115,29.97 arc(117.81,28.09) 121.12,27.43 136.41,27.43 arc(138.36,27.82) 140.01,28.93 140.19,29.1 arc(141.66,31.3) 142.18,33.9 142.18,34.61 arc(142.25,34.98) 142.46,35.29 arc(143.16,35.76) P2.2
UNNAMED_5_CAP_I113_N1: length 38
  BOTTOM w0.127: P1.2 arc(143.32,79.93) 142.75,79.55 arc(142.41,79.04) 142.29,78.43 142.29,76.79 arc(141.84,74.54) 140.57,72.63 arc(139.43,71.87) 138.09,71.6 L30.2 120.22,71.6 arc(117.92,72.06) 115.96,73.36 115.74,73.59 arc(114.8,75) C45.1
UNNAMED_5_CAP_I114_N1: length 30.5
  BOTTOM w0.127: C46.1 116.92,78.64 arc(117.62,78.5) 118.22,78.1 122.54,73.78 arc(123.09,73.42) 123.73,73.29 L34.2 134.32,73.29 arc(134.81,73.34) 135.27,73.5 arc(135.38,73.57) 135.47,73.65 135.47,73.65 arc(135.82,74.17) 135.94,74.79 135.94,77.2 arc(136.17,78.33) 136.81,79.28 arc(137.68,79.86) 138.71,80.07 P1.1
UNNAMED_5_CAP_I115_N1: length 31.2
  BOTTOM w0.127: C47.1 116.6,85.83 arc(117.38,85.99) 118.04,86.43 121.94,90.33 arc(122.52,90.72) 123.2,90.86 L35.2 135.06,90.86 arc(135.47,90.77) 135.83,90.54 135.83,90.54 arc(136.12,90.1) 136.23,89.57 136.23,85.87 arc(136.34,85.28) 136.68,84.77 136.69,84.76 arc(137.46,84.25) 138.37,84.07 P1.4
UNNAMED_5_CAP_I116_N1: length 37.3
  BOTTOM w0.127: C48.1 arc(114.42,89.29) 115.25,90.52 arc(117.5,92.03) 120.16,92.56 L36.2 134.56,92.56 arc(136.86,92.3) 139.03,91.52 arc(139.46,91.3) 139.88,91.05 arc(141.59,89.24) 142.21,86.83 142.21,85.85 arc(142.74,84.59) P1.3
UNNAMED_5_CHOKE2P_I17_N1: length 12.4
  BOTTOM w0.508: R213.2 124.07,98.94 125.02,99.9 L4.2 131.97,99.9 L8.1 132.02,99.89 R11.1
UNNAMED_5_CHOKE2P_I17_N2: length 5.2
  BOTTOM w0.508: R11.2 134.34,97.85 133.83,97.34 132.02,97.34 L8.2 131.44,97.33 L14.1
UNNAMED_5_CHOKE2P_I22_N1: length 12.7
  BOTTOM w0.508: R212.2 123.43,85.15 125.25,83.34 L3.2 132,83.34 L7.1 132.02,83.32 R10.1
UNNAMED_5_CHOKE2P_I22_N2: length 5.4
  BOTTOM w0.508: R10.2 134.32,85.52 133.96,85.88 L7.2 131.39,85.88 L13.1
UNNAMED_5_CHOKE2P_I26_N1: length 12.3
  BOTTOM w0.508: R9.1 132.02,80.81 L6.1 131.98,80.8 L2.2 124.8,80.8 124.15,80.15 R210.2
UNNAMED_5_CHOKE2P_I26_N2: length 5.3
  BOTTOM w0.508: R9.2 134.32,78.64 133.96,78.28 L6.2 131.39,78.28 L12.1
UNNAMED_5_CHOKE2P_I37_N1: length 12.6
  BOTTOM w0.508: R209.2 123.87,65.72 125.36,64.23 L1.2 131.98,64.23 L5.1 132.02,64.2 R8.1
UNNAMED_5_CHOKE2P_I37_N2: length 5.2
  BOTTOM w0.508: L9.1 131.34,66.75 L5.2 133.81,66.75 134.32,66.24 R8.2
UNNAMED_5_CHOKE2P_I61_N1: length 12.7
  BOTTOM w0.508: R16.1 132.04,39.15 L19.1 126.63,39.19 L15.2 125.24,39.2 123.48,40.96 R236.2
UNNAMED_5_CHOKE2P_I61_N2: length 5.3
  BOTTOM w0.508: L23.1 131.34,41.73 L19.2 133.9,41.73 134.32,41.32 R16.2
UNNAMED_5_CHOKE2P_I65_N1: length 12.1
  BOTTOM w0.508: R19.1 132.02,36.64 L22.1 126.63,36.65 L18.2 122.58,36.66 R246.2
UNNAMED_5_CHOKE2P_I65_N2: length 5.4
  BOTTOM w0.508: L26.1 131.34,34.11 L22.2 133.96,34.11 134.32,34.47 R19.2
UNNAMED_5_CHOKE2P_I76_N1: length 12.4
  BOTTOM w0.508: R18.1 132.02,20.08 L21.1 126.62,20.09 L17.2 124.87,20.1 124,20.97 R245.2
UNNAMED_5_CHOKE2P_I76_N2: length 5.3
  BOTTOM w0.508: L25.1 131.34,22.63 L21.2 133.85,22.63 134.32,22.17 R18.2
UNNAMED_5_CHOKE2P_I80_N1: length 12.4
  BOTTOM w0.508: R244.2 123.95,54.77 124.95,55.77 L16.2 126.63,55.75 L20.1 132.02,55.77 R17.1
UNNAMED_5_CHOKE2P_I80_N2: length 5.3
  BOTTOM w0.508: L24.1 131.34,53.21 L20.2 132.02,53.23 133.81,53.23 134.32,53.73 R17.2
UNNAMED_5_IND_I125_N1: length 2.4
  BOTTOM w0.508: L30.1 132.18,70.33 L9.2
UNNAMED_5_IND_I126_N1: length 2.3
  BOTTOM w0.508: L34.1 133.37,74.56 132.28,74.56 L12.2
UNNAMED_5_IND_I127_N1: length 2.3
  BOTTOM w0.508: L35.1 132.23,89.59 L13.2
UNNAMED_5_IND_I128_N1: length 2.2
  BOTTOM w0.508: L14.2 132.13,93.83 L36.1
UNNAMED_5_IND_I129_N1: length 2.3
  BOTTOM w0.508: L25.2 132.08,26.16 L38.1
UNNAMED_5_IND_I130_N1: length 2.4
  BOTTOM w0.508: L26.2 132.13,30.48 L39.1
UNNAMED_5_IND_I131_N1: length 2.4
  BOTTOM w0.508: L40.1 132.16,45.29 L23.2
UNNAMED_5_IND_I132_N1: length 2.3
  BOTTOM w0.508: L37.1 132.03,49.66 L24.2
UNNAMED_6_CN240PABCD_I1_N1: length 1.7
  TOP w0.356: P3.A1 R247.1
UNNAMED_6_CN240PABCD_I2_N36: length 10.7
  TOP w0.249: P3.B36 90.29,93.91 v2(90.35,93.97)
  BOTTOM w0.127: R160.2 90.65,90.77 90.78,90.9 91.39,90.9 91.52,91.02 91.52,91.28 91.39,91.41 90.78,91.41 90.65,91.53 90.65,91.79 90.78,91.91 91.39,91.91 91.52,92.04 91.52,92.29 91.39,92.42 90.5,92.42 90.35,92.57 v2(90.35,93.97)
UNNAMED_6_CN240PABCD_I2_N37: length 13.7
  TOP w0.203: P3.B37 v2(90.93,93.99)
  BOTTOM w0.127: v2(90.93,93.99) 91.39,93.99 92.38,92.99 92.38,90.09 92.26,89.96 91.57,89.96 91.45,89.83 91.45,89.58 91.57,89.45 92.26,89.45 92.38,89.33 92.38,89.07 92.26,88.94 91.57,88.94 91.45,88.82 91.45,88.56 91.57,88.44 92.26,88.44 92.38,88.31 92.38,88.06 92.26,87.93 91.57,87.93 91.45,87.8 91.45,87.55 91.57,87.42 92.26,87.42 92.38,87.29 R159.2
UNNAMED_6_CN240PABCD_I3_N34: length 12.6
  TOP w0.249: P3.C34 89.38,95.57 v2(89.38,95.58)
  BOTTOM w0.127: v2(89.38,95.58) 91.53,95.58 93.24,93.87 R162.2
UNNAMED_6_CN240PABCD_I3_N35: length 13.4
  TOP w0.249: v2(89.57,94.6) 89.66,94.69 P3.C35
  BOTTOM w0.127: v2(89.57,94.6) 89.23,94.26 89.23,92.62 89.05,92.44 88.61,92.44 88.48,92.32 88.48,92.06 88.61,91.94 89.22,91.94 89.35,91.81 89.35,91.56 89.22,91.43 88.61,91.43 88.48,91.3 88.48,91.05 88.61,90.92 89.22,90.92 89.35,90.79 89.35,90.54 89.22,90.41 88.61,90.41 88.48,90.29 88.48,90.03 88.61,89.9 89.22,89.9 89.35,89.78 89.35,89.52 89.22,89.4 88.61,89.4 88.48,89.27 88.48,89.02 88.92,88.58 R161.2
UNNAMED_6_CN240PABCD_I3_N36: length 8.3
  TOP w0.203: P3.C36 v2(90.29,94.6)
  BOTTOM w0.127: v2(90.29,94.6) 89.78,94.09 R163.2
UNNAMED_6_CN240PABCD_I4_N34: length 10.4
  TOP w0.249: P3.D34 v2(89.02,96.53)
  BOTTOM w0.127: R164.2 88.05,93.28 88.67,93.9 88.67,95.8 89.02,96.15 v2(89.02,96.53)
UNNAMED_8_CAP_I21_N1: length 5.4
  TOP w0.203: v2(72.37,14.25) 73.08,14.95 73.08,17.6 v5(73.35,17.87)
  BOTTOM w0.254: v2(72.37,14.25) R135.1 72.37,15.53 C253.1
UNNAMED_8_ICFT230XQ_I40_RESET: length 2.6
  BOTTOM w0.305: U23.9 79.6,10.84 79.29,10.53 R182.1 77.62,10.53 R181.2
UNNAMED_9_741G126_I105_A: length 3.9
  TOP w0.203: R27.2 R185.2 R29.2 74.01,105.12 73.77,105.37 U14.2
UNNAMED_9_741G126_I105_Y: length 2.7
  TOP w0.203: R37.1 69.49,107.35 69.49,106.6 70.08,106.02 U14.4
UNNAMED_9_AD9545_I1_CSB: length 4.8
  TOP w0.203: R35.2 R36.2 94.43,100.6 94.74,100.91 95.5,100.91 96.09,101.5 96.09,102.5 U3.5
UNNAMED_9_AD9545_I1_LDO0: length 4.4
  TOP w0.203: U3.7 97.13,102.5 97.13,100.28 C100.1 C96.1
UNNAMED_9_AD9545_I1_LDO1: length 4
  TOP w0.203: v2(97.13,110.71) 97.13,109.54 U3.30
  BOTTOM w0.203: C113.2 97.13,109.31 v2(97.13,110.71) 97.13,111.42 C116.1
UNNAMED_9_AD9545_I1_LF0: length 3
  TOP w0.203: U3.8 97.61,101.59 97.61,100.23 C100.2
UNNAMED_9_AD9545_I1_LF1: length 3.3
  TOP w0.203: U3.29 97.61,110.53 v2(97.79,110.71)
  BOTTOM w0.203: C113.1 97.79,109.31 v2(97.79,110.71)
UNNAMED_9_AD9545_I1_M0: length 3.1
  TOP w0.203: U3.32 96.1,109.53 96.1,110.4 96.73,111.03 96.73,111.31 R43.2 R44.1
UNNAMED_9_AD9545_I1_M3: length 3.6
  TOP w0.203: R40.2 R204.1 92.85,110.57 93.66,110.57 94.1,110.12 94.1,109.53 U3.36
UNNAMED_9_AD9545_I1_M4: length 3.6
  TOP w0.203: R38.2 R39.1 92.27,110.03 92.27,109.26 92.76,108.77 U3.37
UNNAMED_9_AD9545_I1_REFA: length 3.5
  TOP w0.203: R188.2 R190.1 91.69,102.64 92.83,103.77 U3.47
UNNAMED_9_AD9545_I1_SCLK: length 3.5
  TOP w0.203: U3.2 94.61,101.94 92.87,100.21 R33.2
UNNAMED_9_AD9545_I1_SDIO: length 4.1
  TOP w0.203: U3.4 95.63,102.5 95.63,101.63 95.33,101.32 94.56,101.32 93.66,100.42 R34.2
UNNAMED_9_AD9545_I1_SDO: length 3.6
  TOP w0.203: U3.1 94.11,102.13 92.09,100.1 R32.2
UNNAMED_9_AD9545_I1_XOA: length 6.1
  TOP w0.152: Y3.3 87.98,106.43 88.13,106.28 90.23,106.28 C108.2 90.45,106.27 92.84,106.27 U3.42
UNNAMED_9_AD9545_I1_XOB: length 4.4
  TOP w0.152: U3.43 92.77,105.77 90.45,105.77 C107.1 90.23,105.77 89.35,105.77 Y3.1
UNNAMED_9_ADM7154_I145_BYP: length 1.5
  TOP w0.305: U17.3 115.74,113.39 C225.1
UNNAMED_9_ADM7154_I145_REF: length 3.7
  TOP w0.305: R105.2 C234.1 C233.1 U17.6
UNNAMED_9_ADM7154_I145_REFSENSE: length 2.8
  TOP w0.305: R227.1 R105.1 120.28,112.57 119.95,112.89 U17.5
UNNAMED_9_ADM7154_I145_VOUT: length 2.4
  TOP w0.305: 115.47,113.89 U17.2
  TOP w0.406: 115.47,113.89 C109.1 E2.1
UNNAMED_9_ADM7154_I145_VREG: length 2.5
  TOP w0.305: C118.1 115.71,115.02 116.34,114.39 U17.1
UNNAMED_9_CNBNC5P_I111_CNTR: length 4.7
  TOP w0.203: J1.1 R27.1
UNNAMED_9_CNBNC5P_I136_CNTR: length 4.7
  TOP w0.203: J2.1 R28.1
UNNAMED_9_IC24XX16_I42_SCL: length 4.9
  BOTTOM w0.203: R54.1 95.46,112.92 95.33,113.06 95.33,114.17 94.77,114.73 93.8,114.73 93.4,115.14 U15.6
UNNAMED_9_IC24XX16_I42_SDA: length 4.2
  BOTTOM w0.203: U15.5 93.37,113.87 93.79,114.29 94.56,114.29 94.89,113.96 94.89,113.06 94.76,112.92 R58.1
UNNAMED_9_IC24XX16_I42_WP: length 2.7
  BOTTOM w0.305: U15.7 R49.1 R48.2
UNNAMED_9_RES_I92_N2: length 2.8
  TOP w0.203: Y4.3 97.91,112.6 R44.2
UNNAMED_9_RES_I132_N1: length 3.7
  TOP w0.203: R28.2 R30.1 68.41,106.02 68.99,106.6 68.99,107.35 R31.1
UNNAMED_10_CAP_I6_N2: length 2.8
  BOTTOM w0.305: R55.1 104.74,110.12 C120.2 102.98,110.12 R46.2 R47.1
UNNAMED_10_CAP_I19_N2: length 2.8
  BOTTOM w0.305: R57.1 104.74,101.92 C122.2 102.98,101.92 R53.1 R52.2
UNNAMED_10_CAP_I32_N2: length 4.1
  TOP w0.305: R208.1 R207.1 105.59,105.12 C268.2 C267.2 108.71,105.12 R89.1
UNNAMED_10_CAP_I47_N2: length 2.8
  TOP w0.305: R88.1 C148.2 105.66,101.61 R86.2 R87.1
UNNAMED_10_CAP_I52_N2: length 35.4
  TOP w0.203: J4.1 124.66,106.02 125.35,105.34 125.35,102.1 124.14,100.89 114.55,100.89 113.49,101.95 113.49,104.9 112.54,105.84 111.35,105.84 110.31,106.88 C150.2
UNNAMED_10_CAP_I59_N2: length 2.8
  TOP w0.305: R139.1 C151.2 105.66,109.39 R128.1 R92.2
UNNAMED_10_CNBNC5P_I40_CNTR: length 36.5
  TOP w0.203: J3.1 126.7,106.02 126.01,105.33 126.01,101.83 124.41,100.23 114.27,100.23 112.83,101.68 112.83,104.62 112.27,105.18 111.35,105.18 110.34,104.17 C149.2
UNNAMED_11_CAP_I29_N2: length 4.2
  TOP w0.095: P4.12 40.34,22.34 40.42,22.43 arc(40.61,22.56) 40.84,22.6 43.14,22.6 arc(43.3,22.54) 43.37,22.37 C126.2
UNNAMED_11_CAP_I30_N2: length 4.2
  TOP w0.095: C121.2 43.37,23.12 arc(43.3,22.96) 43.14,22.89 40.84,22.89 arc(40.61,22.94) 40.41,23.07 40.34,23.14 P4.13
UNNAMED_11_CAP_I31_N2: length 4.2
  TOP w0.095: C142.2 43.37,27.17 arc(43.3,27.34) 43.14,27.4 40.84,27.4 arc(40.61,27.36) 40.42,27.23 40.34,27.14 P4.18
UNNAMED_11_CAP_I32_N2: length 4.2
  TOP w0.095: C125.2 43.37,27.92 arc(43.3,27.76) 43.14,27.69 40.84,27.69 arc(40.61,27.74) 40.41,27.87 40.34,27.94 P4.19
UNNAMED_12_DIOLED_I20_N: length 1.3
  TOP w0.406: DS8.C 112.62,17.13 R200.1
UNNAMED_12_DIOLED_I21_N: length 1.3
  TOP w0.406: R202.1 120.31,17.13 DS9.C
UNNAMED_12_DIOLED_I29_N: length 1.3
  TOP w0.406: R205.1 127.98,17.13 DS10.C
UNNAMED_12_DIOLED_I33_N: length 1.3
  TOP w0.406: R206.1 131.7,17.48 DS11.C
UNNAMED_12_DIOLED_I67_N: length 1.4
  TOP w0.406: R153.1 104.95,17.13 DS6.C
UNNAMED_12_RES_I17_N2: length 1.7
  TOP w0.406: R200.2 110.7,16.23 Q6.3
UNNAMED_12_RES_I25_N2: length 1.7
  TOP w0.406: Q12.3 118.4,16.23 R202.2
UNNAMED_12_RES_I28_N2: length 1.7
  TOP w0.406: Q13.3 126.09,16.23 R205.2
UNNAMED_12_RES_I40_N1: length 9.5
  TOP w0.406: R63.1 S1.3
  TOP w0.508: S1.4 S1.3
UNNAMED_12_RES_I42_N1: length 2
  TOP w0.406: R64.1 S2.4B
UNNAMED_12_RES_I44_N1: length 2
  TOP w0.406: R65.1 S2.3B
UNNAMED_12_RES_I46_N1: length 2
  TOP w0.406: R66.1 S2.2B
UNNAMED_12_RES_I49_N1: length 9.6
  TOP w0.406: R67.1 S6.3
  TOP w0.508: S6.3 S6.4
UNNAMED_12_RES_I51_N1: length 2
  TOP w0.406: R68.1 S2.1B
UNNAMED_12_RES_I63_N1: length 9.5
  TOP w0.508: S3.3 S3.4 R219.1
UNNAMED_12_RES_I68_N2: length 1.7
  TOP w0.406: Q3.3 103.01,16.23 R153.2
UNNAMED_13_ADLTC330X_I1_AVIN: length 3.2
  BOTTOM w0.254: R73.2 22.96,46.75 22.96,44.37 23.22,44.11 U6.12
UNNAMED_13_ADLTC330X_I1_FB: length 2.9
  BOTTOM w0.254: U6.10 C135.2 R78.2 R79.1
UNNAMED_13_ADLTC330X_I31_AVIN: length 3.2
  BOTTOM w0.254: R72.2 40.66,46.72 40.66,44.43 40.98,44.11 U5.12
UNNAMED_13_ADLTC330X_I31_FB: length 2.9
  BOTTOM w0.254: R77.1 R76.2 C145.2 U5.10
UNNAMED_13_ADLTC330X_I33_AVIN: length 3.2
  BOTTOM w0.254: U4.12 14.31,44.11 13.99,44.43 13.99,46.74 R71.2
UNNAMED_13_ADLTC330X_I33_FB: length 3.6
  BOTTOM w0.254: U4.10 13.57,43.11 13.28,42.82 C147.2 13.08,42.18 R74.2 R75.1
UNNAMED_13_ADLTC330X_I92_AVIN: length 3.2
  BOTTOM w0.254: U18.12 32.09,44.11 31.77,44.43 31.77,46.72 R228.2
UNNAMED_13_ADLTC330X_I92_FB: length 2.9
  BOTTOM w0.254: U18.10 C146.2 R229.2 R230.1
UNNAMED_14_ADMAX3182X_I77_RSEL: length 1.7
  BOTTOM w0.203: R84.1 140.44,55.94 U7.B3
UNNAMED_14_ADMAX3182X_I78_RSEL: length 1.7
  TOP w0.203: U8.B3 88.18,54.15 88.41,54.38 89.18,54.38 R85.1
UNNAMED_14_CN4P_I63_N3: length 5.2
  TOP w0.356: R103.1 R101.2 50.32,58.44 P6.3
UNNAMED_14_CN4P_I63_N4: length 8.2
  BOTTOM w0.889: Q1.4 55.36,60.9 D1.A 50.91,61.8 P6.4
UNNAMED_14_RES_I58_N2: length 1.6
  BOTTOM w0.483: R98.2 Q1.1
UNNAMED_15_CN2P_I75_N2: length 7.7
  TOP w2.54: P8.2 5.65,93.34 13.28,93.34
UNNAMED_15_CN8PODDEVEN_I74_N3: length 7.4
  TOP w0.356: P13.3 6.63,54.08 13.97,54.08
UNNAMED_15_CN8PODDEVEN_I74_N5: length 7.6
  TOP w0.356: P13.5 7.09,57.23 13.97,57.23
UNNAMED_15_CN8PODDEVEN_I74_N7: length 10.2
  TOP w0.356: v1(11.09,55.64) 11.1,55.65 13.97,55.65
  BOTTOM w0.356: v1(11.09,55.64) 11.09,57.86 9.67,59.28 6.6,59.28 P13.7
UNNAMED_15_CN16PODDEVEN_I72_N1: length 11.4
  TOP w0.356: P12.2 5.32,68.92 8.29,68.92 10.53,66.67 RT9.1
UNNAMED_15_CN16PODDEVEN_I72_N2: length 11.1
  TOP w0.356: RT10.1 10.88,69.82 9.27,71.44 5.29,71.44 P12.4
UNNAMED_15_CN16PODDEVEN_I72_N3: length 10.9
  TOP w0.356: RT11.1 10.82,72.97 9.81,73.98 5.3,73.98 P12.6
UNNAMED_15_CN16PODDEVEN_I72_N4: length 10.9
  TOP w0.356: RT12.1 12.8,76.12 v1(12.45,75.77)
  BOTTOM w0.356: v1(12.45,75.77) 10.03,75.77 9.3,76.49 5.27,76.49 P12.8
UNNAMED_15_CN16PODDEVEN_I72_N5: length 10.9
  TOP w0.356: RT13.1 12.78,77.7 11.58,76.49 5.29,76.49 P12.10
UNNAMED_15_CN16PODDEVEN_I72_N6: length 11.2
  TOP w0.356: RT14.1 12.25,80.85 10.43,79.03 5.3,79.03 P12.12
UNNAMED_15_CN16PODDEVEN_I72_N7: length 11.4
  TOP w0.356: RT15.1 11.93,84 9.52,81.58 5.29,81.58 P12.14
UNNAMED_15_CN16PODDEVEN_I72_N8: length 11.7
  TOP w0.356: RT16.1 10.97,87.15 7.97,84.14 5.26,84.14 P12.16
UNNAMED_15_CN16PODDEVEN_I73_N1: length 8.4
  TOP w0.356: RT1.1 9.07,65.1 P12.1
UNNAMED_15_CN16PODDEVEN_I73_N2: length 8.2
  TOP w0.356: P12.3 9.07,70.15 10.97,68.25 RT2.1
UNNAMED_15_CN16PODDEVEN_I73_N3: length 7.9
  TOP w0.356: RT3.1 10.82,71.4 9.52,72.69 P12.5
UNNAMED_15_CN16PODDEVEN_I73_N4: length 7.7
  TOP w0.356: RT4.1 11.46,74.55 10.78,75.23 P12.7
UNNAMED_15_CN16PODDEVEN_I73_N5: length 8
  TOP w0.356: RT5.1 12.24,79.27 10.74,77.77 P12.9
UNNAMED_15_CN16PODDEVEN_I73_N6: length 8.2
  TOP w0.356: P12.11 9.97,80.31 12.08,82.42 RT6.1
UNNAMED_15_CN16PODDEVEN_I73_N7: length 8.5
  TOP w0.356: P12.13 8.78,82.85 11.5,85.57 RT7.1
UNNAMED_15_CN16PODDEVEN_I73_N8: length 8.8
  TOP w0.356: P12.15 9.88,88.72 RT8.1
UNNAMED_17_ADLTC4355_I29_GATE1: length 5.7
  TOP w0.203: U27.2 29.96,107.9 29.76,107.69 27.68,107.69 27.47,107.89 Q4.4
UNNAMED_17_ADLTC4355_I29_GATE2: length 2.4
  TOP w0.203: Q8.4 31.17,108.39 30.96,108.59 U27.4
UNNAMED_17_ADLTC4355_I29_IN2: length 11.2
  TOP w0.254: U27.5 31.46,109.63
  TOP w0.508: v1(29.84,117.2) R221.1
  L5_PWR w0.508: v1(31.65,109.32) 31.09,109.32 28.98,111.43 28.98,113.05 29.84,113.9 v1(29.84,117.2)
  vias: v1(39.29,106.21) v1(39.29,105.44) v1(39.29,104.68) v1(40.05,106.21) v1(40.05,105.44) v1(40.05,104.68) v1(41.58,106.21) v1(41.58,105.44) v1(41.58,104.68) v1(42.34,106.21) v1(42.34,105.44) v1(42.34,104.68)
UNNAMED_17_ADLTC4355_I29_MON1: length 3.2
  TOP w0.254: R222.1 28.84,114.55 29.46,113.92 U27.14
  TOP w0.508: R221.2 R222.1
UNNAMED_17_ADLTC4355_I29_MON2: length 3.2
  TOP w0.254: R224.1 32.5,114.72 32.42,114.64 32.42,114.64 31.96,114.18 U27.9
  TOP w0.508: R223.2 R224.1
UNNAMED_17_ADLTC4355_I29_SET: length 1.9
  TOP w0.254: R225.1 32.72,114.16 32.46,113.91 U27.8
UNNAMED_17_ADLTC4355_I29_VDSFLTN: length 2.4
  TOP w0.254: U27.6 31.96,109.95 32.26,109.65 33.56,109.65 R226.1
UNNAMED_17_ADMAX2520X_I70_BST: length 2.9
  TOP w0.305: U10.18 v1(34.47,87.45)
  BOTTOM w0.508: C229.1 33.12,87.74 34.15,87.74 34.44,87.45 v1(34.47,87.45)
